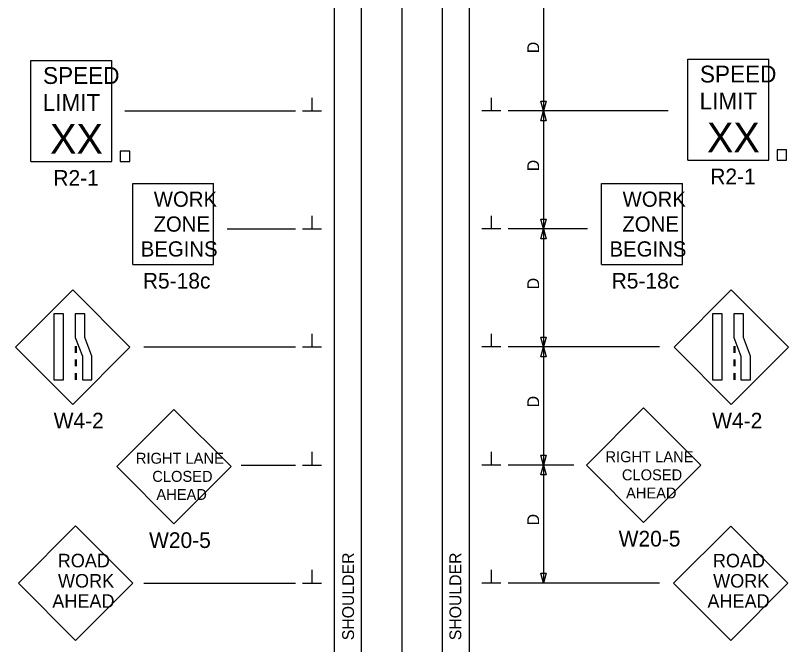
# Model space of a CAD drawing. Extents: x 16738 to 18475, y 6980 to 8209.
# Drawn here: x 16786.1 to 17244.5, y 7456.4 to 7829.5 of the extents above; entities that cross this region are included whole.
import ezdxf

# ---------------------------------------------------------------- set-up
doc = ezdxf.new("R2010")
doc.units = 0
for name, color, linetype in [('ALI_LEGAL_EX', 7, 'Continuous'), ('PAVT_EDGE_EX', 7, 'Continuous'), ('TRAFFIC_SIGNS_PR', 7, 'Continuous'), ('TYPICAL_TEXT_DIMEN_PR', 7, 'Continuous')]:
    doc.layers.add(name, color=color, linetype=linetype)

msp = doc.modelspace()

# ---------------------------------------------------------------- linework, layer by layer
at = {"layer": 'ALI_LEGAL_EX'}
for points in [[(17015.15, 7809.25), (17015.15, 7784.25)], [(17015.15, 7709.25), (17015.15, 7684.25)], [(17015.15, 7609.25), (17015.15, 7584.25)], [(17015.15, 7509.25), (17015.15, 7484.25)]]:
    msp.add_lwpolyline(points, dxfattribs=at)
at = {"layer": 'PAVT_EDGE_EX'}
for p, q in [((16975.15, 8209.25), (16975.15, 7380.06)), ((16991.15, 8209.25), (16991.15, 7380.06)), ((17015.15, 8209.25), (17015.15, 7380.06)), ((17039.15, 8209.25), (17039.15, 7380.06)), ((17055.15, 8209.25), (17055.15, 7380.06))]:
    msp.add_line(p, q, dxfattribs=at)
at = {"layer": 'TRAFFIC_SIGNS_PR'}
for p, q in [((16795.26, 7802.82), (16843.26, 7802.82)), ((16795.26, 7742.82), (16795.26, 7802.82)), ((16843.26, 7742.82), (16843.26, 7802.82)), ((17184.72, 7803.69), (17232.72, 7803.69)), ((17184.72, 7743.69), (17184.72, 7803.69)), ((17232.72, 7743.69), (17232.72, 7803.69)), ((16795.26, 7742.82), (16843.26, 7742.82)), ((17184.72, 7743.69), (17232.72, 7743.69)), ((16855.63, 7681.85), (16855.63, 7729.85)), ((16855.63, 7729.85), (16903.63, 7729.85)), ((16903.63, 7681.85), (16903.63, 7729.85)), ((17133.57, 7681.85), (17133.57, 7729.85)), ((17133.57, 7729.85), (17181.57, 7729.85)), ((17181.57, 7681.85), (17181.57, 7729.85)), ((16855.63, 7681.85), (16903.63, 7681.85)), ((17133.57, 7681.85), (17181.57, 7681.85)), ((16820.07, 7666.76), (16786.13, 7632.82)), ((16854.01, 7632.82), (16820.07, 7666.76)), ((17210.52, 7666.76), (17176.58, 7632.82)), ((17244.46, 7632.82), (17210.52, 7666.76)), ((16786.13, 7632.82), (16820.07, 7598.88)), ((16820.07, 7598.88), (16854.01, 7632.82)), ((16821.62, 7633.44), (16821.62, 7629.44)), ((16822.12, 7633.44), (16822.12, 7629.44)), ((17176.58, 7632.82), (17210.52, 7598.88)), ((17210.52, 7598.88), (17244.46, 7632.82)), ((17212.07, 7633.44), (17212.07, 7629.44)), ((17212.57, 7633.44), (17212.57, 7629.44)), ((16821.62, 7625.44), (16821.62, 7621.44)), ((16822.12, 7625.44), (16822.12, 7621.44)), ((17212.07, 7625.44), (17212.07, 7621.44)), ((17212.57, 7625.44), (17212.57, 7621.44)), ((16821.62, 7617.44), (16821.62, 7613.44)), ((16822.12, 7617.44), (16822.12, 7613.44)), ((17212.07, 7617.44), (17212.07, 7613.44)), ((17212.57, 7617.44), (17212.57, 7613.44)), ((16880.11, 7595.88), (16846.17, 7561.94)), ((16914.05, 7561.94), (16880.11, 7595.88)), ((17158.53, 7596.77), (17124.59, 7562.83)), ((17192.47, 7562.83), (17158.53, 7596.77)), ((17124.59, 7562.83), (17158.53, 7528.88)), ((17158.53, 7528.88), (17192.47, 7562.83)), ((16846.17, 7561.94), (16880.11, 7528)), ((16880.11, 7528), (16914.05, 7561.94)), ((16821.77, 7526.77), (16787.83, 7492.83)), ((16855.71, 7492.83), (16821.77, 7526.77)), ((17210.19, 7526.74), (17176.25, 7492.8)), ((17244.13, 7492.8), (17210.19, 7526.74)), ((16787.83, 7492.83), (16821.77, 7458.88)), ((16821.77, 7458.88), (16855.71, 7492.83)), ((17176.25, 7492.8), (17210.19, 7458.86)), ((17210.19, 7458.86), (17244.13, 7492.8))]:
    msp.add_line(p, q, dxfattribs=at)
for points in [[(16848.27, 7742.82), (16853.87, 7742.82), (16853.87, 7748.99), (16848.27, 7748.99)], [(17237.73, 7743.69), (17243.33, 7743.69), (17243.33, 7749.86), (17237.73, 7749.86)], [(16808.95, 7652.49), (16808.95, 7613.44), (16814.56, 7613.44), (16814.56, 7652.49)], [(16821.62, 7652.49), (16821.62, 7638.52), (16825.8, 7627.41), (16825.8, 7613.44), (16831.42, 7613.44), (16831.42, 7627.41), (16827.24, 7638.52), (16827.24, 7652.49)], [(17199.4, 7652.49), (17199.4, 7613.44), (17205.01, 7613.44), (17205.01, 7652.49)], [(17212.07, 7652.49), (17212.07, 7638.52), (17216.25, 7627.41), (17216.25, 7613.44), (17221.87, 7613.44), (17221.87, 7627.41), (17217.69, 7638.52), (17217.69, 7652.49)]]:
    msp.add_lwpolyline(points, close=True, dxfattribs=at)
at = {"layer": 'TYPICAL_TEXT_DIMEN_PR'}
for p, q in [((17099.15, 7842.9), (17099.15, 7772.9)), ((17099.15, 7797.77), (17099.15, 7794.01)), ((16962.03, 7772.9), (16962.03, 7780.69)), ((17068.28, 7772.9), (17068.28, 7780.69)), ((17099.15, 7772.9), (17097.58, 7778.77)), ((17097.58, 7778.77), (17099.15, 7778.77)), ((17099.15, 7778.77), (17100.72, 7778.77)), ((17100.72, 7778.77), (17099.15, 7772.9)), ((16850.9, 7772.9), (16952.15, 7772.9)), ((16956.4, 7772.9), (16967.65, 7772.9)), ((17073.9, 7772.9), (17062.65, 7772.9)), ((17173.11, 7772.9), (17078.15, 7772.9)), ((17097.58, 7767.04), (17099.15, 7772.9)), ((17099.15, 7772.9), (17099.15, 7702.9)), ((17099.15, 7772.9), (17100.72, 7767.04)), ((17099.15, 7767.04), (17097.58, 7767.04)), ((17100.72, 7767.04), (17099.15, 7767.04)), ((16962.03, 7702.9), (16962.03, 7710.69)), ((17068.28, 7702.9), (17068.28, 7710.69)), ((17099.15, 7702.9), (17097.58, 7708.77)), ((17097.58, 7708.77), (17099.15, 7708.77)), ((17099.15, 7708.77), (17100.72, 7708.77)), ((17100.72, 7708.77), (17099.15, 7702.9)), ((16911.69, 7702.9), (16952.15, 7702.9)), ((16956.4, 7702.9), (16967.65, 7702.9)), ((17073.9, 7702.9), (17062.65, 7702.9)), ((17125.31, 7702.9), (17078.15, 7702.9)), ((17097.58, 7697.04), (17099.15, 7702.9)), ((17099.15, 7702.9), (17100.72, 7697.04)), ((17099.15, 7702.9), (17099.15, 7632.9)), ((17099.15, 7697.04), (17097.58, 7697.04)), ((17100.72, 7697.04), (17099.15, 7697.04)), ((16962.03, 7632.9), (16962.03, 7640.69)), ((17068.28, 7632.9), (17068.28, 7640.69)), ((17099.15, 7632.9), (17097.58, 7638.77)), ((17097.58, 7638.77), (17099.15, 7638.77)), ((17099.15, 7638.77), (17100.72, 7638.77)), ((17100.72, 7638.77), (17099.15, 7632.9)), ((16862.27, 7632.9), (16952.15, 7632.9)), ((16956.4, 7632.9), (16967.65, 7632.9)), ((17073.9, 7632.9), (17062.65, 7632.9)), ((17168.04, 7632.9), (17078.15, 7632.9)), ((17097.58, 7627.04), (17099.15, 7632.9)), ((17099.15, 7632.9), (17099.15, 7562.9)), ((17099.15, 7632.9), (17100.72, 7627.04)), ((17099.15, 7627.04), (17097.58, 7627.04)), ((17100.72, 7627.04), (17099.15, 7627.04)), ((16962.03, 7562.9), (16962.03, 7570.69)), ((17068.28, 7562.9), (17068.28, 7570.69)), ((17099.15, 7562.9), (17097.58, 7568.77)), ((17097.58, 7568.77), (17099.15, 7568.77)), ((17099.15, 7568.77), (17100.72, 7568.77)), ((17100.72, 7568.77), (17099.15, 7562.9)), ((16919.9, 7562.9), (16952.15, 7562.9)), ((16956.4, 7562.9), (16967.65, 7562.9)), ((17073.9, 7562.9), (17062.65, 7562.9)), ((17117.15, 7562.9), (17078.15, 7562.9)), ((17097.58, 7557.04), (17099.15, 7562.9)), ((17099.15, 7562.9), (17099.15, 7492.9)), ((17099.15, 7562.9), (17100.72, 7557.04)), ((17099.15, 7557.04), (17097.58, 7557.04)), ((17100.72, 7557.04), (17099.15, 7557.04)), ((16962.03, 7492.9), (16962.03, 7500.69)), ((17068.28, 7492.9), (17068.28, 7500.69)), ((17099.15, 7492.9), (17097.58, 7498.77)), ((17097.58, 7498.77), (17099.15, 7498.77)), ((17099.15, 7498.77), (17100.72, 7498.77)), ((17100.72, 7498.77), (17099.15, 7492.9)), ((16862.27, 7492.9), (16952.15, 7492.9)), ((16956.4, 7492.9), (16967.65, 7492.9)), ((17073.9, 7492.9), (17062.65, 7492.9)), ((17168.04, 7492.9), (17078.15, 7492.9))]:
    msp.add_line(p, q, dxfattribs=at)

# ---------------------------------------------------------------- texts
at = {"layer": 'TRAFFIC_SIGNS_PR'}
for s, height, p in [('SPEED', 10, (16802.47, 7788.9)), ('SPEED', 10, (17191.93, 7789.76)), ('LIMIT', 10, (16802.26, 7772.9)), ('LIMIT', 10, (17191.72, 7773.76)), ('XX', 17.538, (16806.65, 7747.52)), ('XX', 17.538, (17196.11, 7748.38)), ('R2-1', 9.3, (16808.6, 7728.52)), ('R2-1', 9.3, (17198.06, 7729.39)), ('WORK', 9.021, (16868.13, 7716.06)), ('WORK', 9.021, (17146.07, 7716.06)), ('ZONE', 9.021, (16867.98, 7701.3)), ('ZONE', 9.021, (17145.92, 7701.3)), ('BEGINS', 9.021, (16860.39, 7686.54)), ('BEGINS', 9.021, (17138.33, 7686.54)), ('R5-18c', 9.3, (16861.64, 7667.55)), ('R5-18c', 9.3, (17139.58, 7667.55)), ('W4-2', 9.3, (16808.77, 7584.58)), ('W4-2', 9.3, (17199.21, 7584.58)), ('RIGHT LANE', 6.5, (16857.51, 7563.68)), ('RIGHT LANE', 6.5, (17135.93, 7564.57)), ('CLOSED', 6.5, (16867.25, 7552.93)), ('CLOSED', 6.5, (17145.67, 7553.82)), ('AHEAD', 6.5, (17148.11, 7543.07)), ('AHEAD', 6.5, (16869.68, 7542.18)), ('W20-5', 9.3, (16865.33, 7513.7)), ('W20-5', 9.3, (17143.75, 7514.58)), ('ROAD', 8, (16811.2, 7502.24)), ('ROAD', 8, (17199.62, 7502.22)), ('WORK', 8, (16811.33, 7490.24)), ('WORK', 8, (17199.75, 7490.22)), ('AHEAD', 8, (16807.97, 7478.24)), ('AHEAD', 8, (17196.39, 7478.22))]:
    msp.add_text(s, height=height, dxfattribs=at).set_placement(p)
at = {"layer": 'TYPICAL_TEXT_DIMEN_PR'}
for s, p in [('D', (17096.59, 7807.12)), ('D', (17096.59, 7737.12)), ('D', (17096.59, 7667.12)), ('D', (17096.59, 7597.12)), ('D', (17096.59, 7527.12)), ('SHOULDER', (16986.84, 7459)), ('SHOULDER', (17050.43, 7459))]:
    msp.add_text(s, height=7, rotation=90, dxfattribs=at).set_placement(p)

doc.saveas('drawing.dxf')
